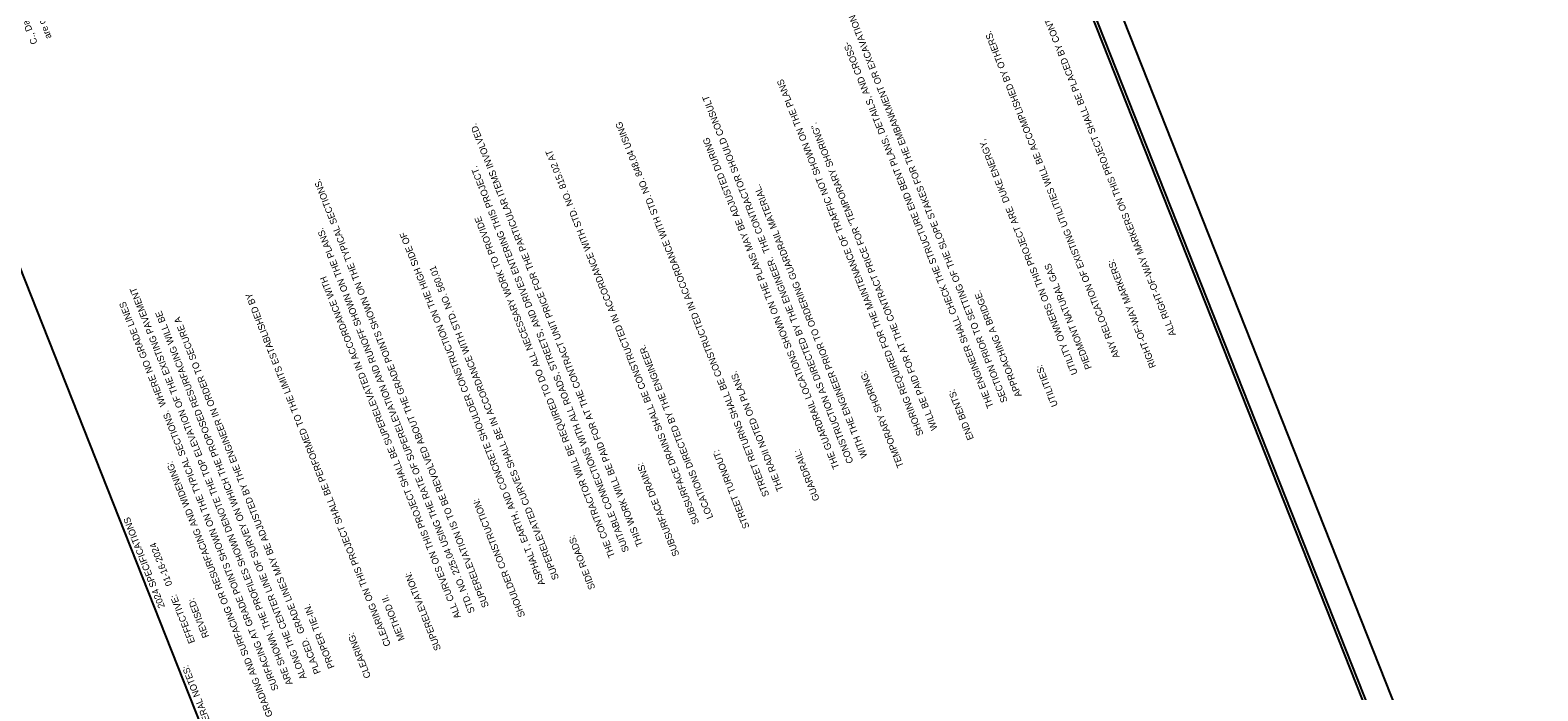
# Model space of a CAD drawing. Extents: x 1247235 to 1260080, y 742320 to 754020.
# Drawn here: x 1254628 to 1260080, y 748302 to 750692 of the extents above; entities that cross this region are included whole.
import ezdxf

# ---------------------------------------------------------------- set-up
doc = ezdxf.new("R2010")
doc.units = 0
for name, color, linetype in [('Scratch_Level_2', 7, 'Continuous'), ('Sheet Data Text CELL', 7, 'Continuous'), ('Sheet Plan CELL', 7, 'Continuous'), ('Sheet Plot Border Inside CELL', 7, 'Continuous'), ('Sheet Plot Border Outside CELL', 7, 'Continuous')]:
    doc.layers.add(name, color=color, linetype=linetype)

msp = doc.modelspace()

# ---------------------------------------------------------------- linework, layer by layer
at = {"layer": 'Scratch_Level_2'}
msp.add_line((1255936.1, 746431.7), (1253258.3, 753203.9), dxfattribs=at)
at = {"layer": 'Sheet Plan CELL'}
msp.add_lwpolyline([(1252801.2, 752166.1), (1255294.6, 745860.4), (1259708.5, 747605.8), (1257215.2, 753911.5)], close=True, dxfattribs=at)
at = {"layer": 'Sheet Plot Border Inside CELL'}
msp.add_lwpolyline([(1259974.2, 746964.6), (1257204.9, 753968.2), (1252769.9, 752214.5), (1255539.2, 745211)], close=True, dxfattribs=at)
at = {"layer": 'Sheet Plot Border Outside CELL'}
msp.add_lwpolyline([(1260079.9, 746943.2), (1257281.5, 754020.3), (1252678.4, 752200.2), (1255476.7, 745123.1)], close=True, dxfattribs=at)

# ---------------------------------------------------------------- texts
at = {"layer": 'Sheet Data Text CELL'}
for s, p in [('C., Dated January 16, 2024 are applicable to this project and by reference hereby ', (1254654.8, 750646.2)), ('are considered a part of these plans:', (1254705.5, 750666.2)), ('         ALL RIGHT-OF-WAY MARKERS ON THIS PROJECT SHALL BE PLACED BY CONTRACT.  ', (1258801, 749515.4)), ('         SECTION PRIOR TO SETTING OF THE SLOPE STAKES FOR THE EMBANKMENT OR EXCAVATION ', (1258192.7, 749274.9)), ('         ANY RELOCATION OF EXISTING UTILITIES WILL BE ACCOMPLISHED BY OTHERS.  ', (1258598.3, 749435.2)), ('         THE ENGINEER SHALL CHECK THE STRUCTURE END BENT PLANS, DETAILS, AND CROSS-', (1258142, 749254.8)), ('         SHORING REQUIRED FOR THE MAINTENANCE OF TRAFFIC NOT SHOWN ON THE PLANS ', (1257888.5, 749154.6)), ('         CONSTRUCTION AS DIRECTED BY THE ENGINEER.  THE CONTRACTOR SHOULD CONSULT', (1257635, 749054.3)), ('         THIS WORK WILL BE PAID FOR AT THE CONTRACT UNIT PRICE FOR THE PARTICULAR ITEMS INVOLVED.  ', (1256874.5, 748753.6)), ('         STREET RETURNS SHALL BE CONSTRUCTED IN ACCORDANCE WITH STD. NO. 848.04 USING ', (1257330.8, 748934.1)), ('         WILL BE PAID FOR AT THE CONTRACT PRICE FOR "TEMPORARY SHORING".', (1257939.2, 749174.6)), ('         THE GUARDRAIL LOCATIONS SHOWN ON THE PLANS MAY BE ADJUSTED DURING ', (1257584.3, 749034.3)), ('         UTILITY OWNERS ON THIS PROJECT ARE  DUKE ENERGY,', (1258446.2, 749375.1)), ('         SUBSURFACE DRAINS SHALL BE CONSTRUCTED IN ACCORDANCE WITH STD. NO. 815.02 AT ', (1257077.3, 748833.8)), ('         SUITABLE CONNECTIONS WITH ALL ROADS, STREETS, AND DRIVES ENTERING THIS PROJECT.  ', (1256823.8, 748733.6)), ('         SUPERELEVATION IS TO BE REVOLVED ABOUT THE GRADE POINTS SHOWN ON THE TYPICAL SECTIONS.  ', (1256316.8, 748533.1)), ('         WITH THE ENGINEER PRIOR TO ORDERING GUARDRAIL MATERIAL.', (1257685.7, 749074.4)), ('         STD. NO. 225.04 USING THE RATE OF SUPERELEVATION AND RUNOFF SHOWN ON THE PLANS.', (1256266.1, 748513.1)), ('         THE CONTRACTOR WILL BE REQUIRED TO DO ALL NECESSARY WORK TO PROVIDE ', (1256773.1, 748713.5)), ('         ASPHALT, EARTH, AND CONCRETE SHOULDER CONSTRUCTION ON THE HIGH SIDE OF', (1256519.6, 748613.3)), ('RIGHT-OF-WAY MARKERS:  ', (1258699.7, 749475.3)), ('         SUPERELEVATED CURVES SHALL BE IN ACCORDANCE WITH STD. NO. 560.01', (1256570.3, 748633.4)), ('         PIEDMONT NATURAL GAS', (1258496.9, 749395.1)), ('         ARE SHOWN, THE PROFILES SHOWN DENOTE THE TOP ELEVATION OF THE EXISTING PAVEMENT ', (1255607, 748252.5)), ('         ALL CURVES ON THIS PROJECT SHALL BE SUPERELEVATED IN ACCORDANCE WITH', (1256215.4, 748493)), ('         SURFACING AT GRADE POINTS SHOWN ON THE TYPICAL SECTIONS.  WHERE NO GRADE LINES ', (1255556.3, 748232.4)), ('         CLEARING ON THIS PROJECT SHALL BE PERFORMED TO THE LIMITS ESTABLISHED BY ', (1255961.9, 748392.8)), ('         APPROACHING A BRIDGE.  ', (1258243.4, 749294.9)), ('         ALONG THE CENTER LINE OF SURVEY ON WHICH THE PROPOSED RESURFACING WILL BE ', (1255657.7, 748272.5)), ('         PLACED.  GRADE LINES MAY BE ADJUSTED BY THE ENGINEER IN ORDER TO SECURE A ', (1255708.4, 748292.6)), ('         LOCATIONS DIRECTED BY THE ENGINEER.  ', (1257128, 748853.9)), ('UTILITIES:  ', (1258344.8, 749335)), ('         THE RADII NOTED ON PLANS.  ', (1257381.5, 748954.1)), ('TEMPORARY SHORING:  ', (1257787.1, 749114.5)), ('END BENTS:  ', (1258040.6, 749214.7)), ('STREET TURNOUT:  ', (1257229.4, 748894)), ('GUARDRAIL:  ', (1257482.9, 748994.2)), ('GRADING AND SURFACING OR RESURFACING AND WIDENING:  ', (1255505.6, 748212.4)), ('SUBSURFACE DRAINS:', (1256975.9, 748793.7)), ('SHOULDER CONSTRUCTION:  ', (1256418.2, 748573.2)), ('GENERAL NOTES:                         2024 SPECIFICATIONS', (1255302.8, 748132.2)), ('                                       EFFECTIVE:    01-16-2024', (1255353.5, 748152.2)), ('SIDE ROADS:  ', (1256671.7, 748673.5)), ('SUPERELEVATION:  ', (1256114, 748452.9)), ('                                       REVISED:      ', (1255404.2, 748172.3)), ('         PROPER TIE-IN.  ', (1255759.1, 748312.6)), ('         METHOD II.', (1256012.6, 748412.8)), ('CLEARING:  ', (1255860.5, 748352.7))]:
    msp.add_text(s, height=24.23, rotation=111.5743, dxfattribs=at).set_placement(p)

doc.saveas('drawing.dxf')
